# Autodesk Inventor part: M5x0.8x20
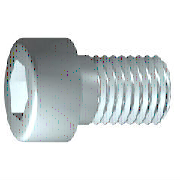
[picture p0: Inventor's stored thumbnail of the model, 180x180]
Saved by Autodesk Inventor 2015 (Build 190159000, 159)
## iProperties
IsCustomPart: 0
Created: 2015-11
Part Number: M5x0.8x20
Material: 스테인리스강
Description: 6각머리 태핑 나사
Document SubType Name: Modeling
Standard: KS B 1003
Designer: mdu
Standards Organization: KS
Language: ko-KR
Size Designation: M 5 x 20
Categories: <MemberInstance><Categories><Category DisplayName="조임쇠" InternalName="e4da775c-781d-43d5-af7c-5136215cf5a6" Mnemonic="FSTN"><Category DisplayName="볼트" InternalN
Density: 8.08 g/cm^3
Appearance: 반광택
Mass: 5.10181 g
Surface Area: 5.88237 cm^2
Volume: 0.631412 cm^3
Author: mdu
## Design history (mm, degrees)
sketch "스케치1"
  geometry: L1 (-1.167, 0)-(20, 0); L2 (20, 0)-(20, 2.5); L3 (20, 2.5)-(2, 2.5); L4 (2, 2.5)-(1.509, 2.5); L5 (1.509, 2.5)-(0, 2.5); L6 (0, 2.5)-(0, 4.25); L7 (0, 4.25)-(-5, 4.25); L8 (-5, 4.25)-(-5, 2.309); L9 (-5, 2.309)-(-2.5, 2.309); L10 (-2.5, 2.309)-(-1.167, 0); L11 (-10, 0)-(25, 0) reference; L12 (0, -0.85)-(0, 5.1) reference; L13 (2, 2.5)-(0, 2.5)
  constraints: 22 end point, 6 parallel, 2 collinear, 2 perpendicular, 1 horizontal, 1 point on line
  dimensions: "d1" = 18 distance from line of L3.end L2 (= GEL); "d2" = 0.49086 distance of L4.end L3.end (computed from GAL); "d3" = 5 distance between parallel lines of L8 L6 (= KOH); "d4" = 2.5 distance of L8.end L9.end (= INTI); "d5" = 60 deg angle of L10 L1; "d6" = 5 diameter of L3 L1 (= GD); "d7" = 5 diameter of L5 L1 (= BDM); "d8" = 4.6188 diameter of L9 L1 (= 1.1547 x SW); "d9" = 8.5 diameter of L7 L1 (= KOD); "d26" = 20 distance between parallel lines of L12 L2 (= NLG)
revolve "본체" sketch "스케치1" stored, may be unused: angle "d10" = 90 deg
sketch "스케치2"
  geometry: L1 (0, -5.95)-(0, 5.95) reference; L2 (-5.95, 0)-(5.95, 0) reference; L3 (2.309, 0)-(1.155, -2); L4 (1.155, -2)-(-1.155, -2); L5 (-1.155, -2)-(-2.309, 0); L6 (-2.309, 0)-(-1.155, 2); L7 (-1.155, 2)-(1.155, 2); L8 (1.155, 2)-(2.309, 0); 2 further points
  constraints: 12 end point, 1 coincident, 1 horizontal alignment, 1 point on line, 12 other
extrude "슬롯" join sketch "스케치2" stored distance "d11" = 10; taper "d12" = 0 deg
workplane "Work Plane1"
fillet "Fillet2" dims "d30" = 0.1 (= R)
body "Solid1"
fillet "모깎기1" dims "d17" = 0.5 (= RR)
feature "스레드" dims "d13" = 18 (= GEL), "d14" = 0
chamfer "모따기1" distance "d15" = 0.49076 (= -0.5 x SPD + 0.5 x GD); stored, may be unused: second distance "d16" = 0.49076 (= GUL), angle "d27" = 45 deg
other parameters: "GD" = 5 (= NND) [user parameter; used in 2 equation terms], "NLG" = 20 [user parameter; used in 1 equation term], "GEL" = 18 [user parameter; used in 2 equation terms], "KOD" = 8.5 [user parameter; used in 1 equation term], "KOH" = 5 [user parameter; used in 1 equation term], "INTI" = 2.5 [user parameter; used in 1 equation term], "GAL" = 0.49076 (= 0.61345 x PTC) [user parameter; used in 1 equation term], "GUL" = 0.49076 (= 0.61345 x PTC) [user parameter; used in 1 equation term], "BDM" = 5 (= NND) [user parameter; used in 1 equation term], "SW" = 4 [user parameter; used in 2 equation terms], "RR" = 0.5 [user parameter; used in 1 equation term], "SPD" = 4.01848 (= NND - 1.2269 x PTC) [user parameter; used in 1 equation term], "d19" = 0, "d28" = 0, "d29" = 0, "R" = 0.1 [user parameter; used in 1 equation term], "PHH" = 0.2 [user parameter], "GD1" = 4.01848 (= THREADDIA - 1.2269 x PTC) [user parameter], "THREADDIA" = 5 [user parameter; used in 1 equation term], "FAWI" = 45 deg [user parameter], "TPU" = 12.5 (computed from PTC) [user parameter], "PTC" = 0.8 [user parameter; used in 5 equation terms], "NND" = 5 [user parameter; used in 3 equation terms], "TOA" = 30 deg [user parameter], "E0" = 4.62 (= 1.155 x SW) [user parameter]
